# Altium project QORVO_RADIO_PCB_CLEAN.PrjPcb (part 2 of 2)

## Sheet Q HE AA.SchDoc
size A; SheetNumber: 16; SheetTotal: 20
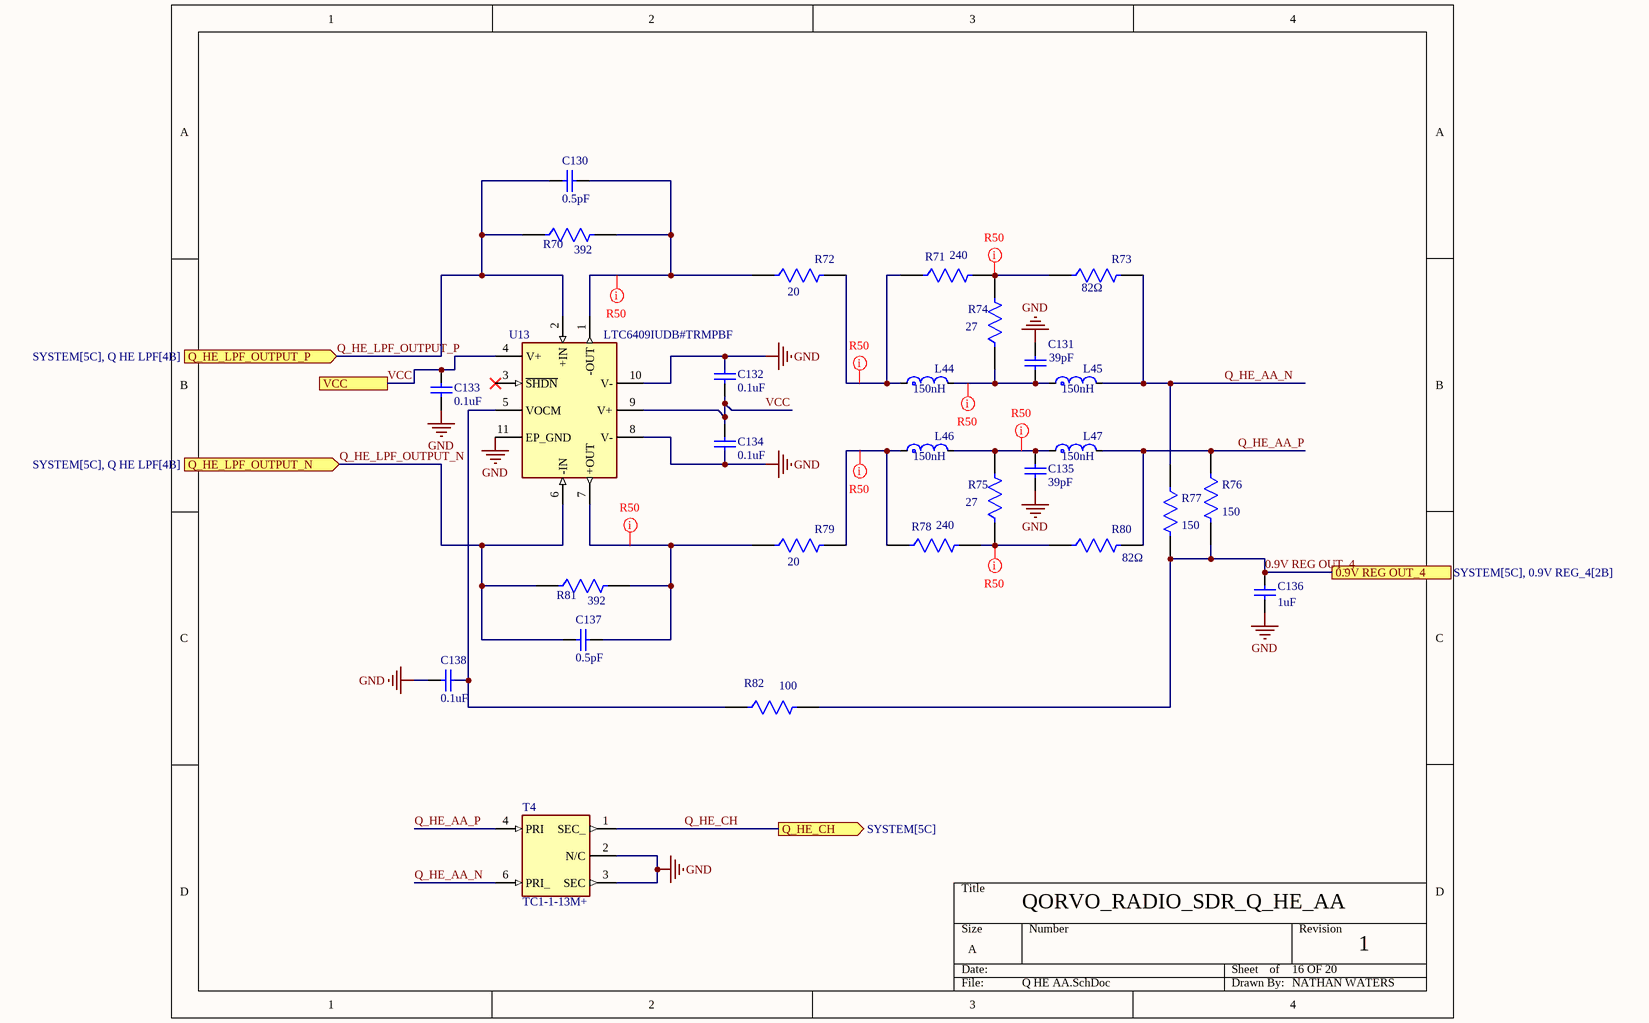
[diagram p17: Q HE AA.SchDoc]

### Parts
C130  CAPACITANCE: 0.5pF  [0402 CAP_IND_RES]  (hidden comment: GJM1555C1HR50CB01D)
C131  CAPACITANCE: 39pF  [0402 CAP_IND_RES]  (hidden comment: GJM1555C1H390JB01D)
C132  CAPACITANCE: 0.1uF  [0402 CAP_IND_RES]  (hidden comment: CL05B104KO5NNNC)
C133  CAPACITANCE: 0.1uF  [0402 CAP_IND_RES]  (hidden comment: CL05B104KO5NNNC)
C134  CAPACITANCE: 0.1uF  [0402 CAP_IND_RES]  (hidden comment: CL05B104KO5NNNC)
C135  CAPACITANCE: 39pF  [0402 CAP_IND_RES]  (hidden comment: GJM1555C1H390JB01D)
C136  CAPACITANCE: 1uF  [0402 CAP_IND_RES]  (hidden comment: GRM155R61H105KE05D)
C137  CAPACITANCE: 0.5pF  [0402 CAP_IND_RES]  (hidden comment: GJM1555C1HR50CB01D)
C138  CAPACITANCE: 0.1uF  [0402 CAP_IND_RES]  (hidden comment: CL05B104KO5NNNC)
L44  Inductance: 150nH  [0402 CAP_IND_RES]  (hidden comment: LQG15HSR15J02D)
L45  Inductance: 150nH  [0402 CAP_IND_RES]  (hidden comment: LQG15HSR15J02D)
L46  Inductance: 150nH  [0402 CAP_IND_RES]  (hidden comment: LQG15HSR15J02D)
L47  Inductance: 150nH  [0402 CAP_IND_RES]  (hidden comment: LQG15HSR15J02D)
R70  Resistance: 392  [0402 CAP_IND_RES]  (hidden comment: RC-02K3920FT)
R71  Resistance: 240  [0402 CAP_IND_RES]  (hidden comment: RC0402FR-07240RL)
R72  Resistance: 20  [0402 CAP_IND_RES]  (hidden comment: CRCW040220R0FKED)
R73  Resistance: 82Ω  [0402 CAP_IND_RES]  (hidden comment: FRC0402F82R0TS)
R74  Resistance: 27  [0402 CAP_IND_RES]  (hidden comment: RC0402FR-0727RL)
R75  Resistance: 27  [0402 CAP_IND_RES]  (hidden comment: RC0402FR-0727RL)
R76  Resistance: 150  [0402 CAP_IND_RES]  (hidden comment: CRCW0402150RFKED)
R77  Resistance: 150  [0402 CAP_IND_RES]  (hidden comment: CRCW0402150RFKED)
R78  Resistance: 240  [0402 CAP_IND_RES]  (hidden comment: RC0402FR-07240RL)
R79  Resistance: 20  [0402 CAP_IND_RES]  (hidden comment: CRCW040220R0FKED)
R80  Resistance: 82Ω  [0402 CAP_IND_RES]  (hidden comment: FRC0402F82R0TS)
R81  Resistance: 392  [0402 CAP_IND_RES]  (hidden comment: RC-02K3920FT)
R82  Resistance: 100  [0402 CAP_IND_RES]  (hidden comment: CRCW0402100RFKEDHP)
T4  TC1-1-13M+  [TC1-1-13M+]
U13  LTC6409IUDB#TRMPBF  [LTC6409IUDB#TRMPBF]

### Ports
0.9V REG OUT_4 (see SYSTEM[5C], 0.9V REG_4[2B]), Q_HE_CH (out, see SYSTEM[5C]), Q_HE_LPF_OUTPUT_N (in, see SYSTEM[5C], Q HE LPF[4B]), Q_HE_LPF_OUTPUT_P (in, see SYSTEM[5C], Q HE LPF[4B]), VCC (see SYSTEM[5C], 0.9V REG_1[3B], 0.9V REG_2[3B], 0.9V REG_3[3B], 0.9V REG_4[3B], 3.3v REG[3B], HE LNA[2A], HE Mixer[3C], I HE AA[1B], I HE LPF[1A], I LE AA[1B], I LE LPF[1A], LE LNA[2A], LE Mixer[3C], Q HE LPF[1A], Q LE AA[1B], Q LE LPF[1B], SWITCH[4B])

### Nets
GND: C131.2 C132.2 C133.1 C134.1 C135.1 C136.1 C138.1 T4.2(N/C) T4.3(SEC) U13.8(V-) U13.10(V-) U13.11(EP_GND)
0.9V REG OUT_4: C136.2 R76.2 R77.2 R82.2 ; port 0.9V REG OUT_4
Q_HE_AA_N: L45.2 R73.2 R77.1 T4.6(PRI_)
Q_HE_AA_P: L47.2 R76.1 R80.2 T4.4(PRI)
Q_HE_CH: T4.1(SEC_) ; port Q_HE_CH  [project net Q HE CH]
Q_HE_LPF_OUTPUT_N: C137.1 R81.1 U13.6(-IN) ; port Q_HE_LPF_OUTPUT_N
Q_HE_LPF_OUTPUT_P: C130.1 R70.1 U13.2(+IN) ; port Q_HE_LPF_OUTPUT_P
VCC: C132.1 C133.2 C134.2 U13.4(V+) U13.9(V+) ; port VCC
NetC130_2: C130.2 R70.2 R72.1 U13.1(-OUT)
NetC131_1: C131.1 L44.2 L45.1 R74.1
NetC135_2: C135.2 L46.2 L47.1 R75.2
NetC137_2: C137.2 R79.1 R81.2 U13.7(+OUT)
NetC138_2: C138.2 R82.1 U13.5(VOCM)
NetL44_1: L44.1 R71.1 R72.2
NetL46_1: L46.1 R78.1 R79.2
NetR71_2: R71.2 R73.1 R74.2
NetR75_1: R75.1 R78.2 R80.1

Not connected (* = marked no-connect by the designer): U13 3(~{SHDN})*

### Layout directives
net class R50: NetC130_2, NetC131_1, NetC135_2, NetC137_2, NetL44_1, NetL46_1, NetR71_2, NetR75_1

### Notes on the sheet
- QORVO_RADIO_SDR_Q_HE_AA
- 16 OF 20
- 1
- NATHAN WATERS

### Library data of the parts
C130 C137 = 0402_CAP: Multi-Layer Ceramic Capacitor 0.5pF C0G  ±0.25pF 0402 Paper T/R
C131 C135 = 0402_CAP: Multi-Layer Ceramic Capacitor 39pF C0G  ±5% 0402 Paper T/R
C132-C134 C138 = 0402_CAP: 16V 100nF X7R ±10% 0402 Multilayer Ceramic Capacitors MLCC - SMD/SMT ROHS
C136 = 0402_CAP: 50V 1uF X5R ±10% 0402  Multilayer Ceramic Capacitors MLCC - SMD/SMT ROHS
L44-L47 = 0402_IND: 150mA 150nH ±5% 2.99Ω 0402 Inductors (SMD) ROHS
R70 = 0402_RES: Thick Film Resistors ±100ppm/℃ ±1% 392Ω 0402  Chip Resistor - Surface Mount ROHS
R71 R78 = 0402_RES: 62.5mW Thick Film Resistors 50V ±100ppm/℃ ±1% 240Ω 0402 Chip Resistor - Surface Mount ROHS
R72 R79 = 0402_RES: RES Thick Film, 20Ω, 1%, 0.063W, 100ppm/°C, 0402
R73 R80 = 0402_RES: 62.5mW Thick Film Resistors 50V ±100ppm/℃ ±1% 82Ω 0402  Chip Resistor - Surface Mount ROHS
R74 R75 = 0402_RES: 62.5mW Thick Film Resistors 50V ±100ppm/℃ ±1% 27Ω 0402 Chip Resistor - Surface Mount ROHS
R76 R77 = 0402_RES: RES Thick Film, 150Ω, 1%, 0.063W, 100ppm/°C, 0402
R81 = 0402_RES: 62.5mW Thick Film Resistors 50V ±1% ±100ppm/℃ 402Ω 0402  Chip Resistor - Surface Mount ROHS
R82 = 0402_RES: 63mW Thick Film Resistors 50V ±100ppm/℃ ±1% 100Ω 0402  Chip Resistor - Surface Mount ROHS
T4 = TC1-1-13M+: SMD,3.8x3.8mm RF Misc ICs and Modules ROHS
U13 = LTC6409IUDB#TRMPBF: QFN-10(2x3)  Differential Amplifiers ROHS; Manufacturer_Name: Analog Devices

## Sheet I HE AA.SchDoc
size A; SheetNumber: 15; SheetTotal: 20
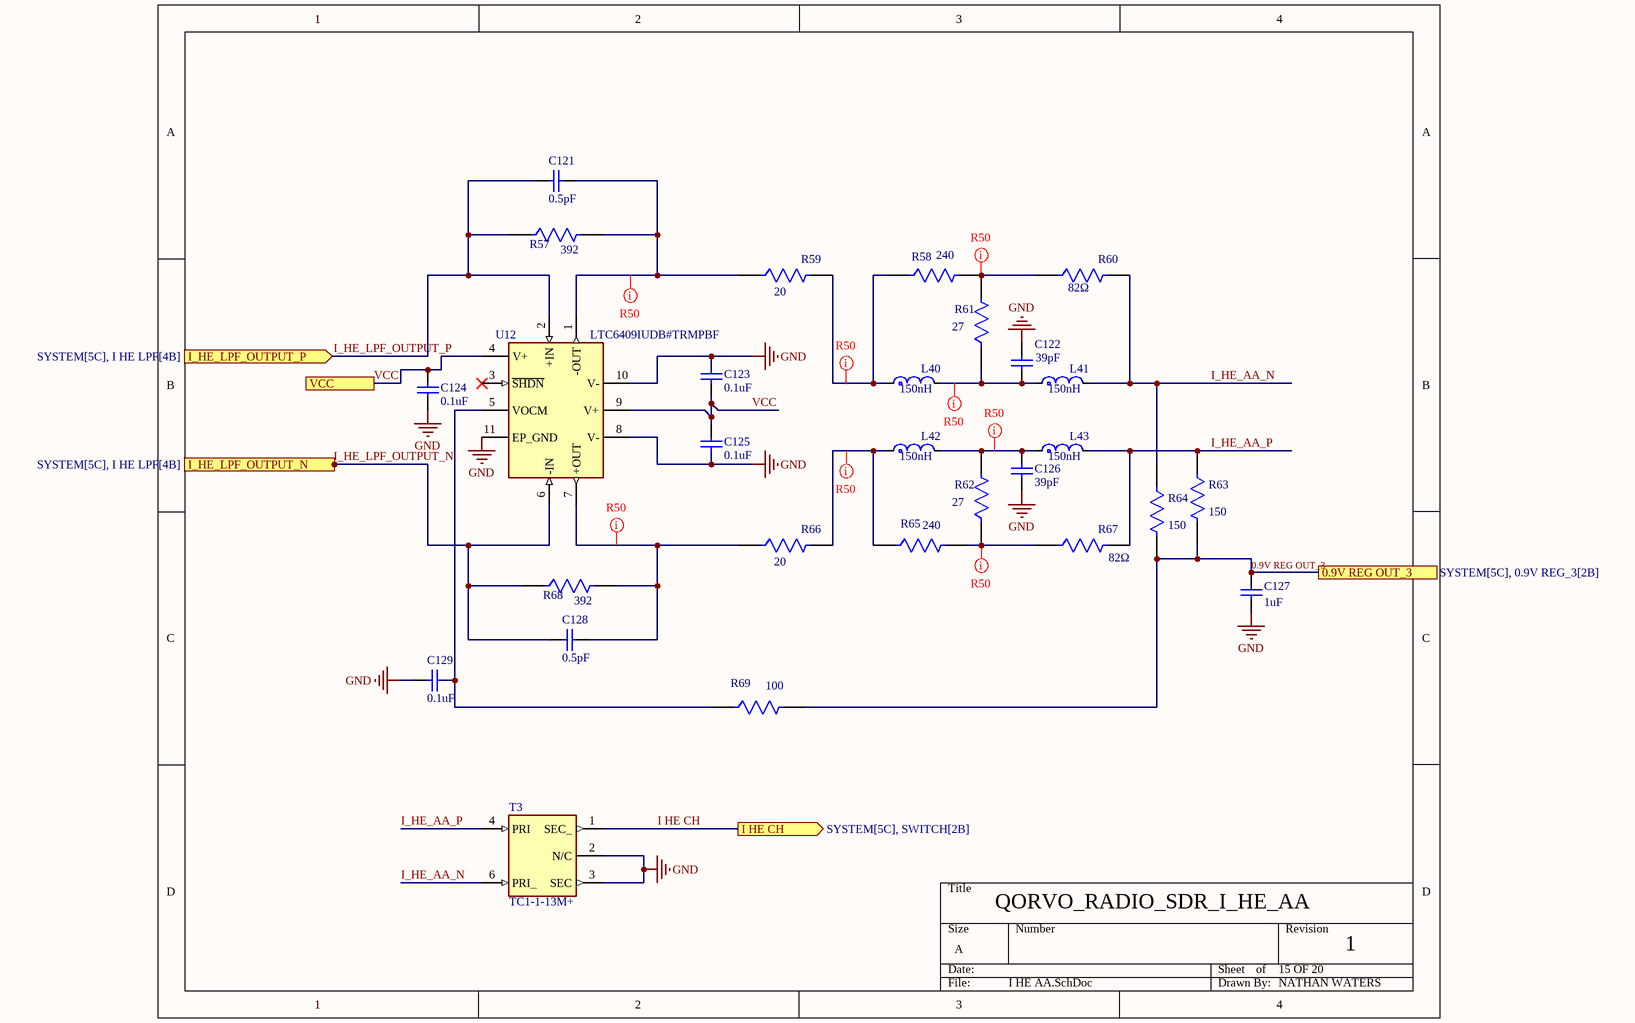
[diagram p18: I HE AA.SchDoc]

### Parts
C121  CAPACITANCE: 0.5pF  [0402 CAP_IND_RES]  (hidden comment: GJM1555C1HR50CB01D)
C122  CAPACITANCE: 39pF  [0402 CAP_IND_RES]  (hidden comment: GJM1555C1H390JB01D)
C123  CAPACITANCE: 0.1uF  [0402 CAP_IND_RES]  (hidden comment: CL05B104KO5NNNC)
C124  CAPACITANCE: 0.1uF  [0402 CAP_IND_RES]  (hidden comment: CL05B104KO5NNNC)
C125  CAPACITANCE: 0.1uF  [0402 CAP_IND_RES]  (hidden comment: CL05B104KO5NNNC)
C126  CAPACITANCE: 39pF  [0402 CAP_IND_RES]  (hidden comment: GJM1555C1H390JB01D)
C127  CAPACITANCE: 1uF  [0402 CAP_IND_RES]  (hidden comment: CL05B104KO5NNNC)
C128  CAPACITANCE: 0.5pF  [0402 CAP_IND_RES]  (hidden comment: GJM1555C1HR50CB01D)
C129  CAPACITANCE: 0.1uF  [0402 CAP_IND_RES]  (hidden comment: CL05B104KO5NNNC)
L40  Inductance: 150nH  [0402 CAP_IND_RES]  (hidden comment: LQG15HSR15J02D)
L41  Inductance: 150nH  [0402 CAP_IND_RES]  (hidden comment: LQG15HSR15J02D)
L42  Inductance: 150nH  [0402 CAP_IND_RES]  (hidden comment: LQG15HSR15J02D)
L43  Inductance: 150nH  [0402 CAP_IND_RES]  (hidden comment: LQG15HSR15J02D)
R57  Resistance: 392  [0402 CAP_IND_RES]  (hidden comment: RC-02K3920FT)
R58  Resistance: 240  [0402 CAP_IND_RES]  (hidden comment: RC0402FR-07240RL)
R59  Resistance: 20  [0402 CAP_IND_RES]  (hidden comment: CRCW040220R0FKED)
R60  Resistance: 82Ω  [0402 CAP_IND_RES]  (hidden comment: FRC0402F82R0TS)
R61  Resistance: 27  [0402 CAP_IND_RES]  (hidden comment: RC0402FR-0727RL)
R62  Resistance: 27  [0402 CAP_IND_RES]  (hidden comment: RC0402FR-0727RL)
R63  Resistance: 150  [0402 CAP_IND_RES]  (hidden comment: CRCW0402150RFKED)
R64  Resistance: 150  [0402 CAP_IND_RES]  (hidden comment: CRCW0402150RFKED)
R65  Resistance: 240  [0402 CAP_IND_RES]  (hidden comment: RC0402FR-07240RL)
R66  Resistance: 20  [0402 CAP_IND_RES]  (hidden comment: CRCW040220R0FKED)
R67  Resistance: 82Ω  [0402 CAP_IND_RES]  (hidden comment: FRC0402F82R0TS)
R68  Resistance: 392  [0402 CAP_IND_RES]  (hidden comment: RC-02K3920FT)
R69  Resistance: 100  [0402 CAP_IND_RES]  (hidden comment: CRCW0402100RFKEDHP)
T3  TC1-1-13M+  [TC1-1-13M+]
U12  LTC6409IUDB#TRMPBF  [LTC6409IUDB#TRMPBF]

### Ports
0.9V REG OUT_3 (see SYSTEM[5C], 0.9V REG_3[2B]), I HE CH (out, see SYSTEM[5C], SWITCH[2B]), I_HE_LPF_OUTPUT_N (in, see SYSTEM[5C], I HE LPF[4B]), I_HE_LPF_OUTPUT_P (in, see SYSTEM[5C], I HE LPF[4B]), VCC (see SYSTEM[5C], 0.9V REG_1[3B], 0.9V REG_2[3B], 0.9V REG_3[3B], 0.9V REG_4[3B], 3.3v REG[3B], HE LNA[2A], HE Mixer[3C], I HE LPF[1A], I LE AA[1B], I LE LPF[1A], LE LNA[2A], LE Mixer[3C], Q HE AA[1B], Q HE LPF[1A], Q LE AA[1B], Q LE LPF[1B], SWITCH[4B])

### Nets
GND: C122.2 C123.2 C124.1 C125.1 C126.1 C127.1 C129.1 T3.2(N/C) T3.3(SEC) U12.8(V-) U12.10(V-) U12.11(EP_GND)
0.9V REG OUT_3: C127.2 R63.2 R64.2 R69.2 ; port 0.9V REG OUT_3
I HE CH: T3.1(SEC_) ; port I HE CH
I_HE_AA_N: L41.2 R60.2 R64.1 T3.6(PRI_)
I_HE_AA_P: L43.2 R63.1 R67.2 T3.4(PRI)
I_HE_LPF_OUTPUT_N: C128.1 R68.1 U12.6(-IN) ; port I_HE_LPF_OUTPUT_N
I_HE_LPF_OUTPUT_P: C121.1 R57.1 U12.2(+IN) ; port I_HE_LPF_OUTPUT_P
VCC: C123.1 C124.2 C125.2 U12.4(V+) U12.9(V+) ; port VCC
NetC121_2: C121.2 R57.2 R59.1 U12.1(-OUT)
NetC122_1: C122.1 L40.2 L41.1 R61.1
NetC126_2: C126.2 L42.2 L43.1 R62.2
NetC128_2: C128.2 R66.1 R68.2 U12.7(+OUT)
NetC129_2: C129.2 R69.1 U12.5(VOCM)
NetL40_1: L40.1 R58.1 R59.2
NetL42_1: L42.1 R65.1 R66.2
NetR58_2: R58.2 R60.1 R61.2
NetR62_1: R62.1 R65.2 R67.1

Not connected (* = marked no-connect by the designer): U12 3(~{SHDN})*

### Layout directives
net class R50: NetC121_2, NetC122_1, NetC126_2, NetC128_2, NetL40_1, NetL42_1, NetR58_2, NetR62_1

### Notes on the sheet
- QORVO_RADIO_SDR_I_HE_AA
- 15 OF 20
- 1
- NATHAN WATERS

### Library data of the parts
C121 C128 = 0402_CAP: as C130 on sheet Q HE AA
C122 C126 = 0402_CAP: as C131 on sheet Q HE AA
C123-C125 C129 = 0402_CAP: as C132-C134 on sheet Q HE AA
C127 = 0402_CAP: as C136 on sheet Q HE AA
L40-L43 = 0402_IND: as L44 on sheet Q HE AA
R57 R68 = 0402_RES: as R70 on sheet Q HE AA
R58 R65 = 0402_RES: as R71 on sheet Q HE AA
R59 R66 = 0402_RES: as R72 on sheet Q HE AA
R60 R67 = 0402_RES: as R73 on sheet Q HE AA
R61 R62 = 0402_RES: as R74 on sheet Q HE AA
R63 R64 = 0402_RES: as R76 on sheet Q HE AA
R69 = 0402_RES: as R82 on sheet Q HE AA
T3 = TC1-1-13M+: as T4 on sheet Q HE AA
U12 = LTC6409IUDB#TRMPBF: as U13 on sheet Q HE AA

## Sheet Q LE AA.SchDoc
size A; SheetNumber: 14; SheetTotal: 20
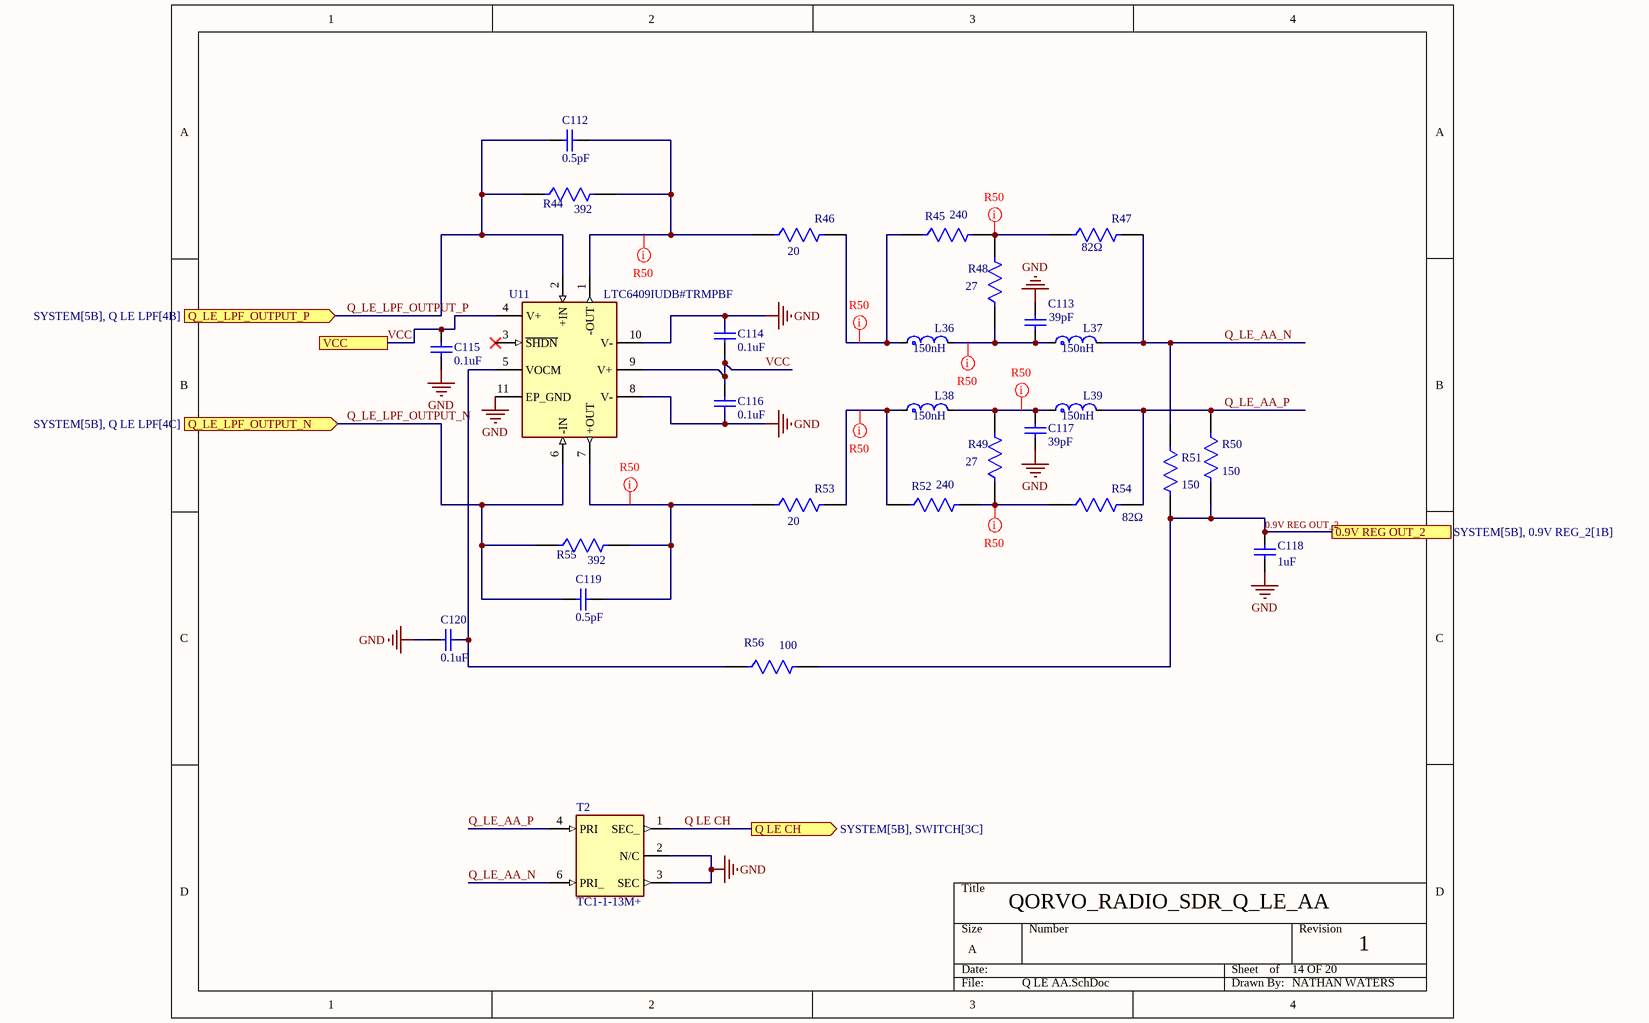
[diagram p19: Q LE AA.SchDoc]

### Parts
C112  CAPACITANCE: 0.5pF  [0402 CAP_IND_RES]  (hidden comment: GJM1555C1HR50CB01D)
C113  CAPACITANCE: 39pF  [0402 CAP_IND_RES]  (hidden comment: GJM1555C1H390JB01D)
C114  CAPACITANCE: 0.1uF  [0402 CAP_IND_RES]  (hidden comment: CL05B104KO5NNNC)
C115  CAPACITANCE: 0.1uF  [0402 CAP_IND_RES]  (hidden comment: CL05B104KO5NNNC)
C116  CAPACITANCE: 0.1uF  [0402 CAP_IND_RES]  (hidden comment: CL05B104KO5NNNC)
C117  CAPACITANCE: 39pF  [0402 CAP_IND_RES]  (hidden comment: GJM1555C1H390JB01D)
C118  CAPACITANCE: 1uF  [0402 CAP_IND_RES]  (hidden comment: GRM155R61H105KE05D)
C119  CAPACITANCE: 0.5pF  [0402 CAP_IND_RES]  (hidden comment: GJM1555C1HR50CB01D)
C120  CAPACITANCE: 0.1uF  [0402 CAP_IND_RES]  (hidden comment: CL05B104KO5NNNC)
L36  Inductance: 150nH  [0402 CAP_IND_RES]  (hidden comment: LQG15HSR15J02D)
L37  Inductance: 150nH  [0402 CAP_IND_RES]  (hidden comment: LQG15HSR15J02D)
L38  Inductance: 150nH  [0402 CAP_IND_RES]  (hidden comment: LQG15HSR15J02D)
L39  Inductance: 150nH  [0402 CAP_IND_RES]  (hidden comment: LQG15HSR15J02D)
R44  Resistance: 392  [0402 CAP_IND_RES]  (hidden comment: RC-02K3920FT)
R45  Resistance: 240  [0402 CAP_IND_RES]  (hidden comment: RC0402FR-07240RL)
R46  Resistance: 20  [0402 CAP_IND_RES]  (hidden comment: CRCW040220R0FKED)
R47  Resistance: 82Ω  [0402 CAP_IND_RES]  (hidden comment: FRC0402F82R0TS)
R48  Resistance: 27  [0402 CAP_IND_RES]  (hidden comment: RC0402FR-0727RL)
R49  Resistance: 27  [0402 CAP_IND_RES]  (hidden comment: RC0402FR-0727RL)
R50  Resistance: 150  [0402 CAP_IND_RES]  (hidden comment: CRCW0402150RFKED)
R51  Resistance: 150  [0402 CAP_IND_RES]  (hidden comment: CRCW0402150RFKED)
R52  Resistance: 240  [0402 CAP_IND_RES]  (hidden comment: CRCW0402243RFKED)
R53  Resistance: 20  [0402 CAP_IND_RES]  (hidden comment: CRCW040220R0FKED)
R54  Resistance: 82Ω  [0402 CAP_IND_RES]  (hidden comment: FRC0402F82R0TS)
R55  Resistance: 392  [0402 CAP_IND_RES]  (hidden comment: RC-02K3920FT)
R56  Resistance: 100  [0402 CAP_IND_RES]  (hidden comment: CRCW0402100RFKEDHP)
T2  TC1-1-13M+  [TC1-1-13M+]
U11  LTC6409IUDB#TRMPBF  [LTC6409IUDB#TRMPBF]

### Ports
0.9V REG OUT_2 (see SYSTEM[5B], 0.9V REG_2[1B]), Q LE CH (out, see SYSTEM[5B], SWITCH[3C]), Q_LE_LPF_OUTPUT_N (in, see SYSTEM[5B], Q LE LPF[4C]), Q_LE_LPF_OUTPUT_P (in, see SYSTEM[5B], Q LE LPF[4B]), VCC (see SYSTEM[5B], 0.9V REG_1[3B], 0.9V REG_2[3B], 0.9V REG_3[3B], 0.9V REG_4[3B], 3.3v REG[3B], HE LNA[2A], HE Mixer[3C], I HE AA[1B], I HE LPF[1A], I LE AA[1B], I LE LPF[1A], LE LNA[2A], LE Mixer[3C], Q HE AA[1B], Q HE LPF[1A], Q LE LPF[1B], SWITCH[4B])

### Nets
GND: C113.2 C114.2 C115.1 C116.1 C117.1 C118.1 C120.1 T2.2(N/C) T2.3(SEC) U11.8(V-) U11.10(V-) U11.11(EP_GND)
0.9V REG OUT_2: C118.2 R50.2 R51.2 R56.2 ; port 0.9V REG OUT_2
Q LE CH: T2.1(SEC_) ; port Q LE CH
Q_LE_AA_N: L37.2 R47.2 R51.1 T2.6(PRI_)
Q_LE_AA_P: L39.2 R50.1 R54.2 T2.4(PRI)
Q_LE_LPF_OUTPUT_N: C119.1 R55.1 U11.6(-IN) ; port Q_LE_LPF_OUTPUT_N
Q_LE_LPF_OUTPUT_P: C112.1 R44.1 U11.2(+IN) ; port Q_LE_LPF_OUTPUT_P
VCC: C114.1 C115.2 C116.2 U11.4(V+) U11.9(V+) ; port VCC
NetC112_2: C112.2 R44.2 R46.1 U11.1(-OUT)
NetC113_1: C113.1 L36.2 L37.1 R48.1
NetC117_2: C117.2 L38.2 L39.1 R49.2
NetC119_2: C119.2 R53.1 R55.2 U11.7(+OUT)
NetC120_2: C120.2 R56.1 U11.5(VOCM)
NetL36_1: L36.1 R45.1 R46.2
NetL38_1: L38.1 R52.1 R53.2
NetR45_2: R45.2 R47.1 R48.2
NetR49_1: R49.1 R52.2 R54.1

Not connected (* = marked no-connect by the designer): U11 3(~{SHDN})*

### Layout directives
net class R50: NetC112_2, NetC113_1, NetC117_2, NetC119_2, NetL36_1, NetL38_1, NetR45_2, NetR49_1

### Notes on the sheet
- QORVO_RADIO_SDR_Q_LE_AA
- 14 OF 20
- 1
- NATHAN WATERS

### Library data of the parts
C112 C119 = 0402_CAP: as C130 on sheet Q HE AA
C113 C117 = 0402_CAP: as C131 on sheet Q HE AA
C114-C116 C120 = 0402_CAP: as C132-C134 on sheet Q HE AA
C118 = 0402_CAP: CAPACITOR
L36-L39 = 0402_IND: as L44 on sheet Q HE AA
R44 R55 = 0402_RES: as R70 on sheet Q HE AA
R45 R52 = 0402_RES: as R71 on sheet Q HE AA
R46 R53 = 0402_RES: as R72 on sheet Q HE AA
R47 R54 = 0402_RES: as R73 on sheet Q HE AA
R48 R49 = 0402_RES: as R74 on sheet Q HE AA
R50 R51 = 0402_RES: as R76 on sheet Q HE AA
R56 = 0402_RES: as R82 on sheet Q HE AA
T2 = TC1-1-13M+: as T4 on sheet Q HE AA
U11 = LTC6409IUDB#TRMPBF: as U13 on sheet Q HE AA

## Sheet I LE AA.SchDoc
size A; SheetNumber: 13; SheetTotal: 20
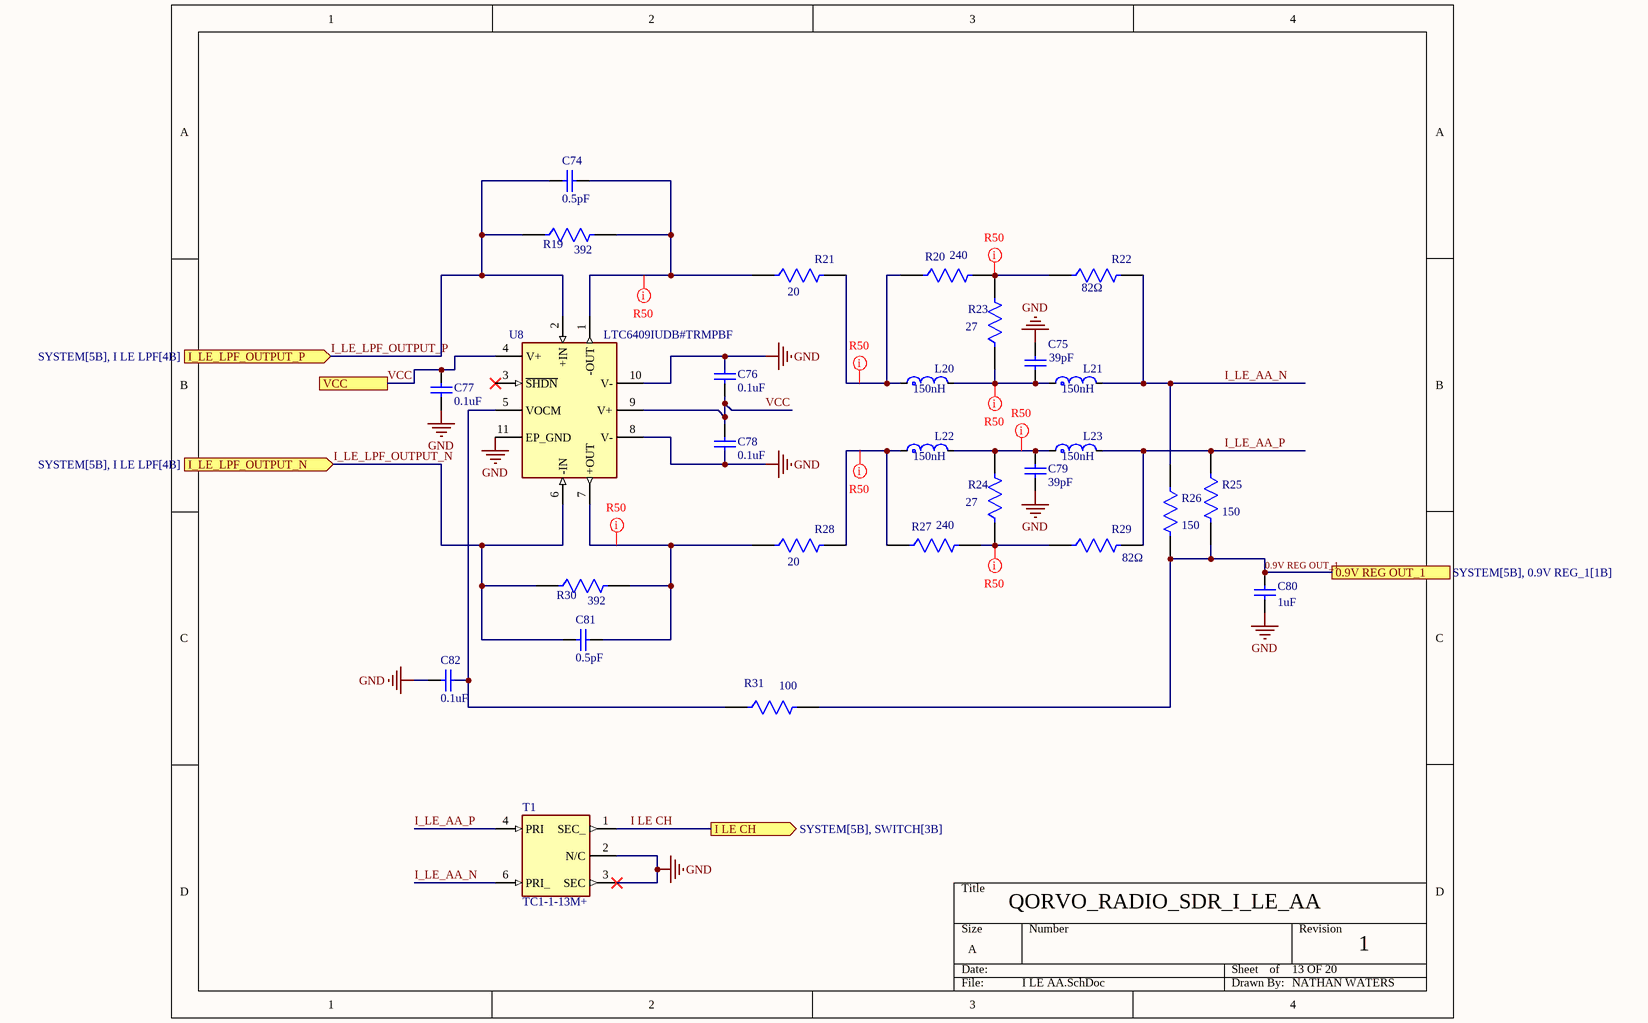
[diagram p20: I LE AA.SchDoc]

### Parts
C74  CAPACITANCE: 0.5pF  [0402 CAP_IND_RES]  (hidden comment: GJM1555C1HR50CB01D)
C75  CAPACITANCE: 39pF  [0402 CAP_IND_RES]  (hidden comment: GJM1555C1H390JB01D)
C76  CAPACITANCE: 0.1uF  [0402 CAP_IND_RES]  (hidden comment: CL05B104KO5NNNC)
C77  CAPACITANCE: 0.1uF  [0402 CAP_IND_RES]  (hidden comment: CL05B104KO5NNNC)
C78  CAPACITANCE: 0.1uF  [0402 CAP_IND_RES]  (hidden comment: CL05B104KO5NNNC)
C79  CAPACITANCE: 39pF  [0402 CAP_IND_RES]  (hidden comment: GJM1555C1H390JB01D)
C80  CAPACITANCE: 1uF  [0402 CAP_IND_RES]  (hidden comment: GRM155R61H105KE05D)
C81  CAPACITANCE: 0.5pF  [0402 CAP_IND_RES]  (hidden comment: GJM1555C1HR50CB01D)
C82  CAPACITANCE: 0.1uF  [0402 CAP_IND_RES]  (hidden comment: CL05B104KO5NNNC)
L20  Inductance: 150nH  [0402 CAP_IND_RES]  (hidden comment: LQG15HSR15J02D)
L21  Inductance: 150nH  [0402 CAP_IND_RES]  (hidden comment: LQG15HSR15J02D)
L22  Inductance: 150nH  [0402 CAP_IND_RES]  (hidden comment: LQG15HSR15J02D)
L23  Inductance: 150nH  [0402 CAP_IND_RES]  (hidden comment: LQG15HSR15J02D)
R19  Resistance: 392  [0402 CAP_IND_RES]  (hidden comment: RC-02K3920FT)
R20  Resistance: 240  [0402 CAP_IND_RES]  (hidden comment: RC0402FR-07240RL)
R21  Resistance: 20  [0402 CAP_IND_RES]  (hidden comment: CRCW040220R0FKED)
R22  Resistance: 82Ω  [0402 CAP_IND_RES]  (hidden comment: FRC0402F82R0TS)
R23  Resistance: 27  [0402 CAP_IND_RES]  (hidden comment: RC0402FR-0727RL)
R24  Resistance: 27  [0402 CAP_IND_RES]  (hidden comment: RC0402FR-0727RL)
R25  Resistance: 150  [0402 CAP_IND_RES]  (hidden comment: CRCW0402150RFKED)
R26  Resistance: 150  [0402 CAP_IND_RES]  (hidden comment: CRCW0402150RFKED)
R27  Resistance: 240  [0402 CAP_IND_RES]  (hidden comment: RC0402FR-07240RL)
R28  Resistance: 20  [0402 CAP_IND_RES]  (hidden comment: CRCW040220R0FKED)
R29  Resistance: 82Ω  [0402 CAP_IND_RES]  (hidden comment: FRC0402F82R0TS)
R30  Resistance: 392  [0402 CAP_IND_RES]  (hidden comment: RC-02K3920FT)
R31  Resistance: 100  [0402 CAP_IND_RES]  (hidden comment: CRCW0402100RFKEDHP)
T1  TC1-1-13M+  [TC1-1-13M+]
U8  LTC6409IUDB#TRMPBF  [LTC6409IUDB#TRMPBF]

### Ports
0.9V REG OUT_1 (see SYSTEM[5B], 0.9V REG_1[1B]), I LE CH (out, see SYSTEM[5B], SWITCH[3B]), I_LE_LPF_OUTPUT_N (in, see SYSTEM[5B], I LE LPF[4B]), I_LE_LPF_OUTPUT_P (in, see SYSTEM[5B], I LE LPF[4B]), VCC (see SYSTEM[5B], 0.9V REG_1[3B], 0.9V REG_2[3B], 0.9V REG_3[3B], 0.9V REG_4[3B], 3.3v REG[3B], HE LNA[2A], HE Mixer[3C], I HE AA[1B], I HE LPF[1A], I LE LPF[1A], LE LNA[2A], LE Mixer[3C], Q HE AA[1B], Q HE LPF[1A], Q LE AA[1B], Q LE LPF[1B], SWITCH[4B])

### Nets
GND: C75.2 C76.2 C77.1 C78.1 C79.1 C80.1 C82.1 T1.2(N/C) T1.3(SEC) U8.8(V-) U8.10(V-) U8.11(EP_GND)
0.9V REG OUT_1: C80.2 R25.2 R26.2 R31.2 ; port 0.9V REG OUT_1
I LE CH: T1.1(SEC_) ; port I LE CH
I_LE_AA_N: L21.2 R22.2 R26.1 T1.6(PRI_)
I_LE_AA_P: L23.2 R25.1 R29.2 T1.4(PRI)
I_LE_LPF_OUTPUT_N: C81.1 R30.1 U8.6(-IN) ; port I_LE_LPF_OUTPUT_N
I_LE_LPF_OUTPUT_P: C74.1 R19.1 U8.2(+IN) ; port I_LE_LPF_OUTPUT_P
VCC: C76.1 C77.2 C78.2 U8.4(V+) U8.9(V+) ; port VCC
NetC74_2: C74.2 R19.2 R21.1 U8.1(-OUT)
NetC75_1: C75.1 L20.2 L21.1 R23.1
NetC79_2: C79.2 L22.2 L23.1 R24.2
NetC81_2: C81.2 R28.1 R30.2 U8.7(+OUT)
NetC82_2: C82.2 R31.1 U8.5(VOCM)
NetL20_1: L20.1 R20.1 R21.2
NetL22_1: L22.1 R27.1 R28.2
NetR20_2: R20.2 R22.1 R23.2
NetR24_1: R24.1 R27.2 R29.1

Not connected (* = marked no-connect by the designer): U8 3(~{SHDN})*

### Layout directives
net class R50: NetC74_2, NetC75_1, NetC79_2, NetC81_2, NetL20_1, NetL22_1, NetR20_2, NetR24_1

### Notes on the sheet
- QORVO_RADIO_SDR_I_LE_AA
- 13 OF 20
- 1
- NATHAN WATERS

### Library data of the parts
C74 C81 = 0402_CAP: as C130 on sheet Q HE AA
C75 C79 = 0402_CAP: as C131 on sheet Q HE AA
C76-C78 C82 = 0402_CAP: as C132-C134 on sheet Q HE AA
C80 = 0402_CAP: as C136 on sheet Q HE AA
L20-L23 = 0402_IND: as L44 on sheet Q HE AA
R19 R30 = 0402_RES: as R70 on sheet Q HE AA
R20 R27 = 0402_RES: as R71 on sheet Q HE AA
R21 R28 = 0402_RES: as R72 on sheet Q HE AA
R22 R29 = 0402_RES: as R73 on sheet Q HE AA
R23 R24 = 0402_RES: as R74 on sheet Q HE AA
R25 R26 = 0402_RES: as R76 on sheet Q HE AA
R31 = 0402_RES: as R82 on sheet Q HE AA
T1 = TC1-1-13M+: as T4 on sheet Q HE AA
U8 = LTC6409IUDB#TRMPBF: as U13 on sheet Q HE AA

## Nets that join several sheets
GND: SYSTEM (24 pins), HE LNA (9 pins), 3.3v REG (7 pins), SWITCH (C150.1 U1.3), 0.9V REG_1 (C88.2 C89.2 C90.1 U10.2), 0.9V REG_2 (C139.2 C140.2 C141.1 U14.2), 0.9V REG_3 (C142.2 C143.2 C144.1 U15.2), 0.9V REG_4 (C145.2 C146.2 C147.1 U16.2), LE LNA (12 pins), LE Mixer (7 pins), LO (38 pins), HE Mixer (9 pins), I LE LPF (7 pins), Q LE LPF (7 pins), I HE LPF (7 pins), Q HE LPF (7 pins), Q HE AA (12 pins), I HE AA (12 pins), Q LE AA (12 pins), I LE AA (12 pins)
0.9V REG OUT_1: 0.9V REG_1 (C88.1 U10.1), I LE AA (C80.2 R25.2 R26.2 R31.2)
0.9V REG OUT_2: 0.9V REG_2 (C139.1 U14.1), Q LE AA (C118.2 R50.2 R51.2 R56.2)
0.9V REG OUT_3: 0.9V REG_3 (C142.1 U15.1), I HE AA (C127.2 R63.2 R64.2 R69.2)
0.9V REG OUT_4: 0.9V REG_4 (C145.1 U16.1), Q HE AA (C136.2 R76.2 R77.2 R82.2)
AVDD: 3.3v REG (C85.2 U9.2), LO (22 pins)
CHIP_EN: SYSTEM (J7.7), LO (R9.1 U3.4)
HE LNA OUTPUT: HE LNA (C72.2), HE Mixer (U6.5)
HEM EN: SYSTEM (TPHEMEN.1 U2.18), 0.9V REG_3 (U15.4), 0.9V REG_4 (U16.4), HE Mixer (U6.7)
I HE CH: SWITCH (U1.2), I HE AA (T3.1)
I LE CH: SWITCH (U1.9), I LE AA (T1.1)
I/O_I: SYSTEM (TPSWI.1 U2.21), SWITCH (U1.1)
I/O_Q: SYSTEM (TPSWQ.1 U2.20), SWITCH (U1.5)
I_HE_LPF_INPUT_N: HE Mixer (U6.22), I HE LPF (C102.2 L30.1)
I_HE_LPF_INPUT_P: HE Mixer (U6.23), I HE LPF (C99.1 L28.1)
I_HE_LPF_OUTPUT_N: I HE LPF (R39.2), I HE AA (C128.1 R68.1 U12.6)
I_HE_LPF_OUTPUT_P: I HE LPF (R38.2), I HE AA (C121.1 R57.1 U12.2)
I_LE_LPF_INPUT_N: LE Mixer (U4.22), I LE LPF (C95.2 L26.1)
I_LE_LPF_INPUT_P: LE Mixer (U4.23), I LE LPF (C92.1 L24.1)
I_LE_LPF_OUTPUT_N: I LE LPF (R35.2), I LE AA (C81.1 R30.1 U8.6)
I_LE_LPF_OUTPUT_P: I LE LPF (R34.2), I LE AA (C74.1 R19.1 U8.2)
LE_LNA OUTPUT_N: LE LNA (C58.2), LE Mixer (U4.6)
LE_LNA OUTPUT_P: LE LNA (C56.1), LE Mixer (U4.5)
LEM EN: SYSTEM (TPLEMEN.1 U2.17), 0.9V REG_1 (U10.4), 0.9V REG_2 (U14.4), LE Mixer (U4.7)
LO_HE_OUT_N: LO (L13.2), HE Mixer (U6.16)
LO_HE_OUT_P: LO (L10.2), HE Mixer (U6.15)
LO_LE_OUT_N: LE Mixer (U4.16), LO (C38.2 L14.2)
LO_LE_OUT_P: LE Mixer (U4.15), LO (C27.1 L11.2)
LOAD_EN: SYSTEM (TPLOADEN.1 U2.19), LO (R10.1 R12.2 U3.3)
MOSI: SYSTEM (J7.3 U2.9), LO (R13.2 U3.2)
MUX_OUT: SYSTEM (J7.8 TPMUXOUT.1), LO (U3.30)
NetC53_1: SYSTEM (J3.6), LE LNA (C53.1)
NetC71_1: SYSTEM (J4.6), HE LNA (C71.1)
NetJ5_6: SYSTEM (J5.6), SWITCH (U1.6)
NetJ6_6: SYSTEM (J6.6), SWITCH (U1.10)
Q HE CH: SWITCH (U1.4), Q HE AA (T4.1)
Q LE CH: SWITCH (U1.7), Q LE AA (T2.1)
Q_HE_LPF_INPUT_N: HE Mixer (U6.20), Q HE LPF (C109.2 L34.1)
Q_HE_LPF_INPUT_P: HE Mixer (U6.21), Q HE LPF (C106.1 L32.1)
Q_HE_LPF_OUTPUT_N: Q HE LPF (R43.2), Q HE AA (C137.1 R81.1 U13.6)
Q_HE_LPF_OUTPUT_P: Q HE LPF (R42.2), Q HE AA (C130.1 R70.1 U13.2)
Q_LE_LPF_INPUT_N: LE Mixer (U4.20), Q LE LPF (C5.2 L3.1)
Q_LE_LPF_INPUT_P: LE Mixer (U4.21), Q LE LPF (C2.1 L1.1)
Q_LE_LPF_OUTPUT_N: Q LE LPF (R4.2), Q LE AA (C119.1 R55.1 U11.6)
Q_LE_LPF_OUTPUT_P: Q LE LPF (R3.2), Q LE AA (C112.1 R44.1 U11.2)
REFIN: SYSTEM (J7.6), LO (C9.2)
SCK: SYSTEM (J7.4 U2.8), LO (R14.2 U3.1)
VCC: SYSTEM (J1.1 TPVCC.1 U2.5), HE LNA (C70.1 FB3.2), 3.3v REG (C84.1 U9.7 U9.8), SWITCH (C150.2 U1.8), 0.9V REG_1 (C89.1 U10.6), 0.9V REG_2 (C140.1 U14.6), 0.9V REG_3 (C143.1 U15.6), 0.9V REG_4 (C146.1 U16.6), LE LNA (C52.1 FB1.2), LE Mixer (C50.2 C51.2 U4.10), HE Mixer (C67.2 C69.2 U6.10), I LE LPF (C91.2 R32.1 R33.2), Q LE LPF (C1.2 R1.1 R2.2), I HE LPF (C98.2 R36.1 R37.2), Q HE LPF (C105.2 R40.1 R41.2), Q HE AA (5 pins), I HE AA (5 pins), Q LE AA (5 pins), I LE AA (5 pins)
